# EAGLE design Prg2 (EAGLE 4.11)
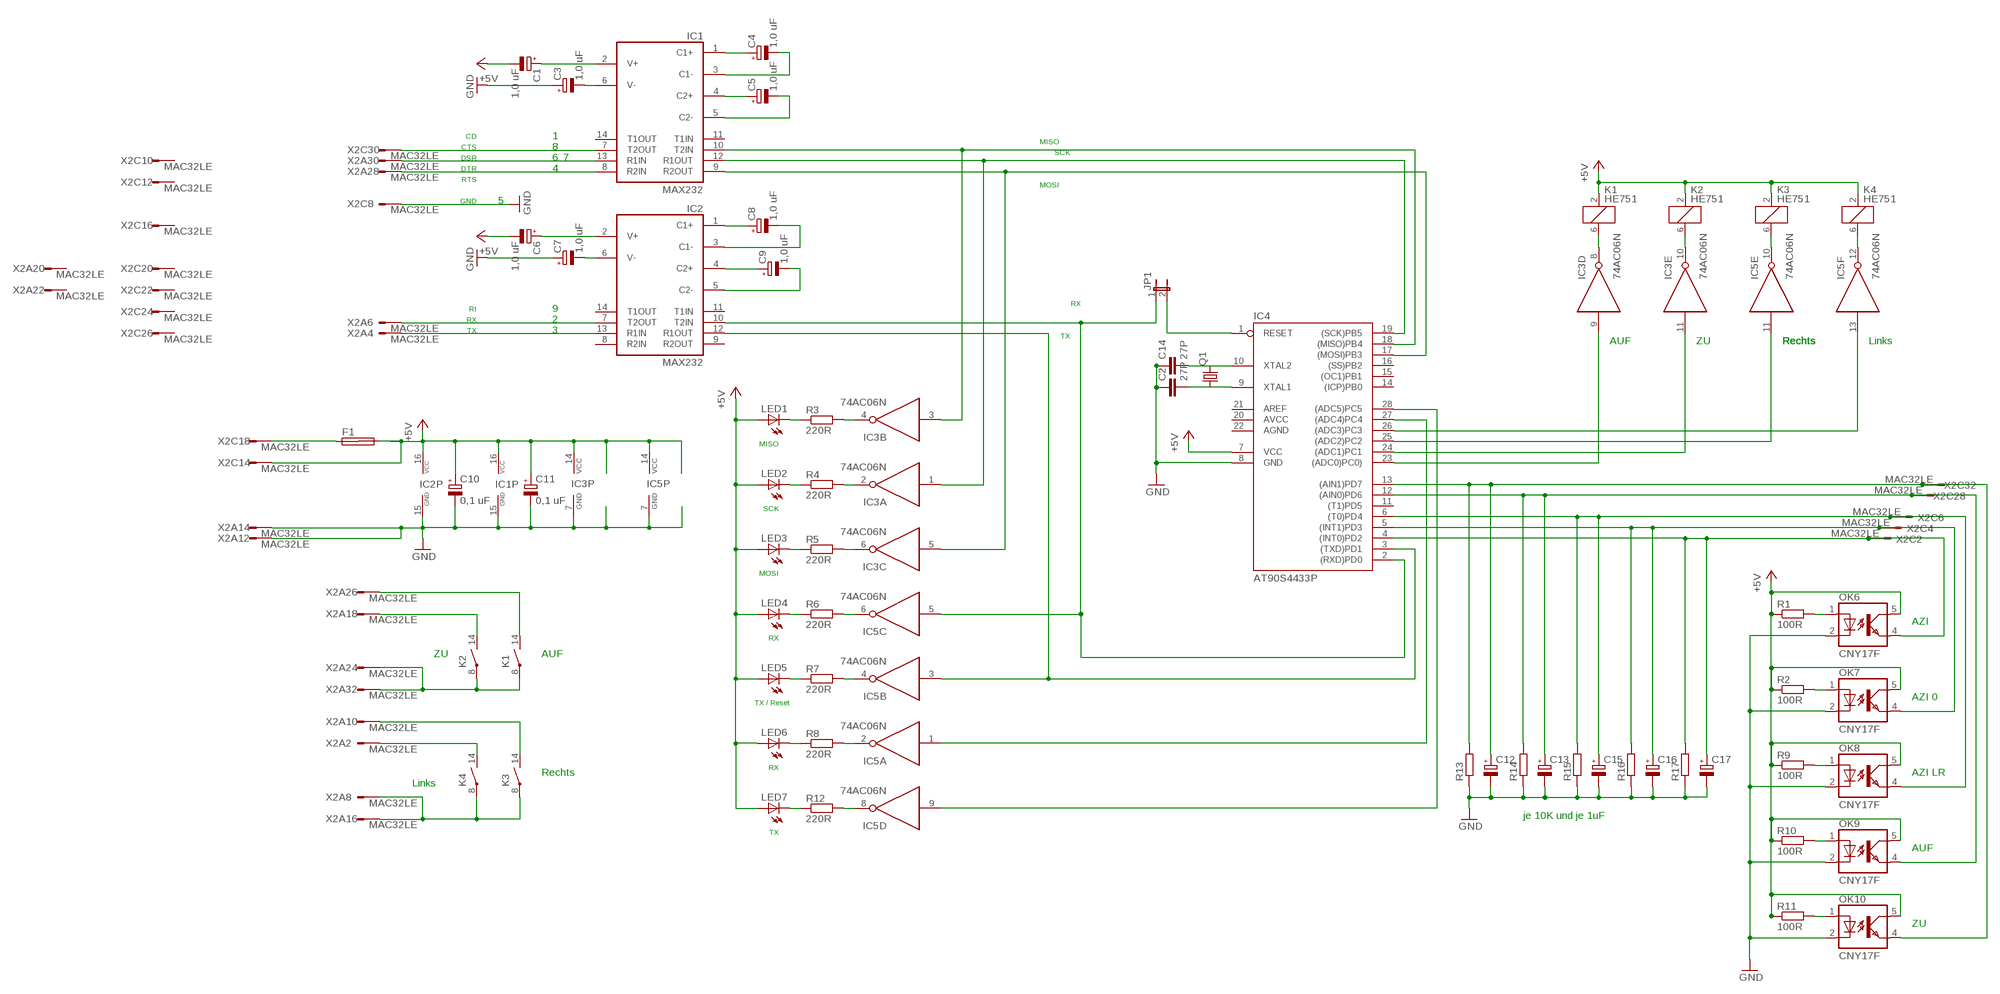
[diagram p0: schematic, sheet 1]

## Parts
C1  1,0 uF  CPOL-EUE2,5-6E  [E2,5-6E]
C2  27P  C-EU025-024X044  [C025-024X044]
C3  1,0 uF  CPOL-EUE2,5-6E  [E2,5-6E]
C4  1,0 uF  CPOL-EUE2,5-6E  [E2,5-6E]
C5  1,0 uF  CPOL-EUE2,5-6E  [E2,5-6E]
C6  1,0 uF  CPOL-EUE2,5-6E  [E2,5-6E]
C7  1,0 uF  CPOL-EUE2,5-6E  [E2,5-6E]
C8  1,0 uF  CPOL-EUE2,5-6E  [E2,5-6E]
C9  1,0 uF  CPOL-EUE2,5-6E  [E2,5-6E]
C10  0,1 uF  CPOL-EUE2,5-6E  [E2,5-6E]
C11  0,1 uF  CPOL-EUE2,5-6E  [E2,5-6E]
C12  CPOL-EUE2,5-6E  [E2,5-6E]
C13  CPOL-EUE2,5-6E  [E2,5-6E]
C14  27P  C-EU025-024X044  [C025-024X044]
C15  CPOL-EUE2,5-6E  [E2,5-6E]
C16  CPOL-EUE2,5-6E  [E2,5-6E]
C17  CPOL-EUE2,5-6E  [E2,5-6E]
F1  SHK20L  [SHK20L]
IC1  MAX232  [DIL16]
IC2  MAX232  [DIL16]
IC3  74AC06N  [DIL14]
IC4  AT90S4433P  [DIL28-3]
IC5  74AC06N  [DIL14]
JP1  JP1E  [JP1]
K1  HE751  [HE751]
K2  HE751  [HE751]
K3  HE751  [HE751]
K4  HE751  [HE751]
LED1  LED3MM  [LED3MM]
LED2  LED3MM  [LED3MM]
LED3  LED3MM  [LED3MM]
LED4  LED3MM  [LED3MM]
LED5  LED3MM  [LED3MM]
LED6  LED3MM  [LED3MM]
LED7  LED3MM  [LED3MM]
OK6  CNY17F  [DIL06]
OK7  CNY17F  [DIL06]
OK8  CNY17F  [DIL06]
OK9  CNY17F  [DIL06]
OK10  CNY17F  [DIL06]
Q1  CRYTALHC49S  [HC49/S]
R1  100R  R-EU_0204/7  [0204/7]
R2  100R  R-EU_0204/7  [0204/7]
R3  220R  R-EU_0207/2V  [0207/2V]
R4  220R  R-EU_0207/2V  [0207/2V]
R5  220R  R-EU_0207/2V  [0207/2V]
R6  220R  R-EU_0207/2V  [0207/2V]
R7  220R  R-EU_0207/2V  [0207/2V]
R8  220R  R-EU_0207/2V  [0207/2V]
R9  100R  R-EU_0204/7  [0204/7]
R10  100R  R-EU_0204/7  [0204/7]
R11  100R  R-EU_0204/7  [0204/7]
R12  220R  R-EU_0207/2V  [0207/2V]
R13  R-EU_0204/2V  [0204V]
R14  R-EU_0204/2V  [0204V]
R15  R-EU_0204/2V  [0204V]
R16  R-EU_0204/2V  [0204V]
R17  R-EU_0204/2V  [0204V]
X2  MAC32LE  [MAC32L]

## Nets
+5V: C1.- C6.- C10.+ C11.+ F1.2A IC1.16(VCC) IC2.16(VCC) IC3.14(P:VCC) IC4.7(VCC) IC5.14(P:VCC) K1.2 K2.2 K3.2 K4.2 LED1.A LED2.A LED3.A LED4.A LED5.A LED6.A LED7.A OK6.5(COL) OK7.5(COL) OK8.5(COL) OK9.5(COL) OK10.5(COL) R1.1 R2.1 R9.1 R10.1 R11.1 X2.C14
GND: C2.1 C3.+ C7.+ C10.- C11.- C12.- C13.- C14.1 C15.- C16.- C17.- IC1.15(GND) IC2.15(GND) IC3.7(P:GND) IC4.8(GND) IC5.7(P:GND) OK6.2(C) OK7.2(C) OK8.2(C) OK9.2(C) OK10.2(C) R13.1 R14.1 R15.1 R16.1 R17.1 X2.A12 X2.A14 X2.C8
N$1: C4.+ IC1.1(C1+)
N$2: C4.- IC1.3(C1-)
N$3: C5.+ IC1.4(C2+)
N$4: C5.- IC1.5(C2-)
N$5: C3.- IC1.6(V-)
N$6: C1.+ IC1.2(V+)
N$7: C6.+ IC2.2(V+)
N$8: C7.- IC2.6(V-)
N$9: C8.+ IC2.1(C1+)
N$10: C9.+ IC2.4(C2+)
N$11: C9.- IC2.5(C2-)
N$12: C8.- IC2.3(C1-)
N$13: K2.14(2:S) X2.A18
N$14: K3.8(2:P) K4.8(2:P) X2.A8 X2.A16
N$15: K3.14(2:S) X2.A10
N$16: K4.14(2:S) X2.A2
N$17: IC1.13(R1IN) X2.A30
N$18: IC1.8(R2IN) X2.A28
N$19: IC2.7(T2OUT) X2.A6
N$20: IC1.9(R2OUT) IC3.5(C:I) IC4.17((MOSI)PB3)
N$21: IC3.8(D:O) K1.6
N$22: IC3.10(E:O) K2.6
N$23: IC2.12(R1OUT) IC4.3((TXD)PD1) IC5.3(B:I)
N$24: IC2.10(T2IN) IC4.2((RXD)PD0) IC5.5(C:I) JP1.1
N$25: LED1.K(C) R3.1
N$26: IC3.4(B:O) R3.2
N$27: LED2.K(C) R4.1
N$28: IC3.2(A:O) R4.2
N$29: LED3.K(C) R5.1
N$30: IC3.6(C:O) R5.2
N$31: LED4.K(C) R6.1
N$32: IC5.6(C:O) R6.2
N$33: LED5.K(C) R7.1
N$34: IC5.4(B:O) R7.2
N$35: C14.2 IC4.10(XTAL2) Q1.2
N$36: C2.2 IC4.9(XTAL1) Q1.1
N$37: IC3.9(D:I) IC4.23((ADC0)PC0))
N$38: IC5.12(F:O) K4.6
N$39: IC4.26((ADC3)PC3) IC5.13(F:I)
N$40: IC5.10(E:O) K3.6
N$41: IC1.10(T2IN) IC3.3(B:I) IC4.18((MISO)PB4)
N$42: IC4.1(RESET) JP1.2
N$43: IC5.2(A:O) R8.2
N$44: IC5.8(D:O) R12.2
N$45: LED6.K(C) R8.1
N$46: LED7.K(C) R12.1
N$47: IC4.27((ADC4)PC4) IC5.1(A:I)
N$48: IC4.28((ADC5)PC5) IC5.9(D:I)
N$49: IC1.12(R1OUT) IC3.1(A:I) IC4.19((SCK)PB5)
N$50: IC3.11(E:I) IC4.24((ADC1)PC1)
N$51: IC4.25((ADC2)PC2) IC5.11(E:I)
N$52: OK6.1(A) R1.2
N$53: OK7.1(A) R2.2
N$54: OK8.1(A) R9.2
N$55: OK9.1(A) R10.2
N$56: OK10.1(A) R11.2
N$57: F1.1A X2.C18
N$59: C16.+ IC4.5((INT1)PD3) OK7.4(EMIT) R16.2 X2.C4
N$60: C15.+ IC4.6((T0)PD4) OK8.4(EMIT) R15.2 X2.C6
N$61: C13.+ IC4.12((AIN0)PD6) OK9.4(EMIT) R14.2 X2.C28
N$62: K1.14(2:S) X2.A26
N$63: C12.+ IC4.13((AIN1)PD7) OK10.4(EMIT) R13.2 X2.C32
N$64: K1.8(2:P) K2.8(2:P) X2.A24 X2.A32
N$65: IC1.7(T2OUT) X2.C30
N$66: IC2.13(R1IN) X2.A4
N$67: C17.+ IC4.4((INT0)PD2) OK6.4(EMIT) R17.2 X2.C2
Unconnected: F1.1B F1.2B IC1.11(T1IN) IC1.14(T1OUT) IC2.8(R2IN) IC2.9(R2OUT) IC2.11(T1IN) IC2.14(T1OUT) IC3.12(F:O) IC3.13(F:I) IC4.11((T1)PD5) IC4.14((ICP)PB0) IC4.15((OC1)PB1) IC4.16((SS)PB2) X2.A20 X2.A22 X2.C10 X2.C12 X2.C16 X2.C20 X2.C22 X2.C24 X2.C26

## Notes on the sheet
- CD | 1 | MISO
- CTS | 8 | SCK
- DSR | 6 | 7
- DTR | 4
- RTS | MOSI
- GND | 5
- RX
- RI | 9
- RX | 2
- TX | 3 | TX
- AUF | ZU | Rechts | Rechts | Links
- MISO
- SCK
- MOSI
- AZI
- RX
- ZU | AUF
- TX / Reset | AZI 0
- RX
- Rechts | AZI LR
- Links
- je 10K und je 1uF
- TX
- AUF
- ZU

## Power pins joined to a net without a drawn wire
AGND: IC4.22(AGND)
AREF: IC4.21(AREF)
AVCC: IC4.20(AVCC)

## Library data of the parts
C1 C3-C13 C15-C17 = rcl:CPOL-EU: POLARIZED CAPACITOR, European symbol
C2 C14 = rcl:C-EU: CAPACITOR, European symbol
F1 = fuse:SHK20L: FUSE HOLDER 5 x 20 mm, SH contact, SHH1 Schukat, E1073 Buerklin
IC1 IC2 = maxim:MAX232: RS232 TRANSEIVER
IC3 IC5 = 74xx-eu:74*06: Hex INVERTER, open collector high-voltage output
IC4 = atmel:AT90S4433: MICROCONTROLLER 4 Kbytes FLASH 128 bytes SRAM 256 bytes EEPROM UART 6-channel 10 bit ADC
JP1 = jumper:JP1E: JUMPER
K1-K4 = relay:HE751: RELAY reed, 1 x norm. open, Hamlin
LED1-LED7 = led:LED: LED
OK6-OK10 = optocoupler:CNY17F: SIEMENS OPTO COUPLER
Q1 = crystal:CRYTAL: CRYSTAL
R1-R17 = rcl:R-EU_: RESISTOR, European symbol
X2 = con-vg:MAC32LE: CONNECTOR male, 32 pins, single, type D, rows AC, grid 5.08 mm with mounting clip

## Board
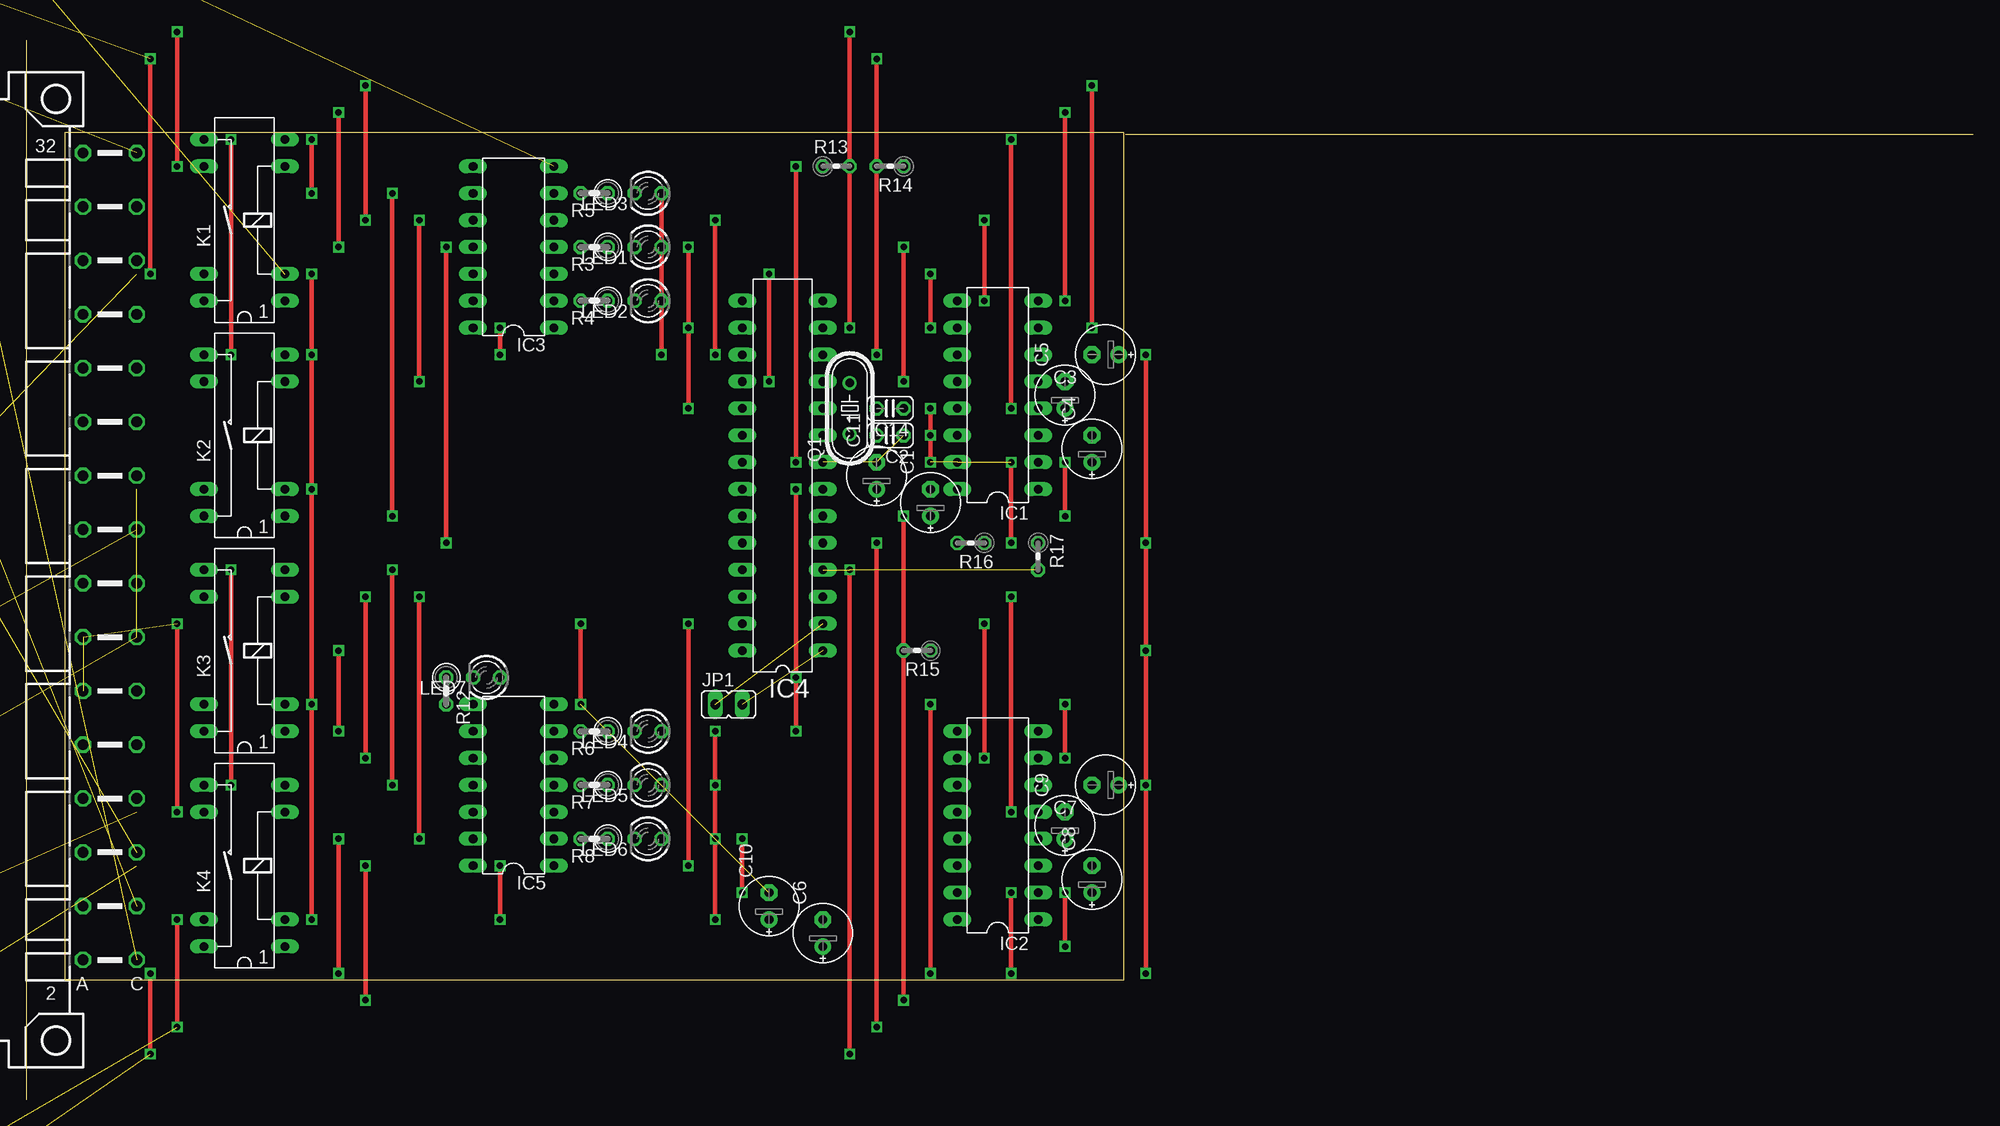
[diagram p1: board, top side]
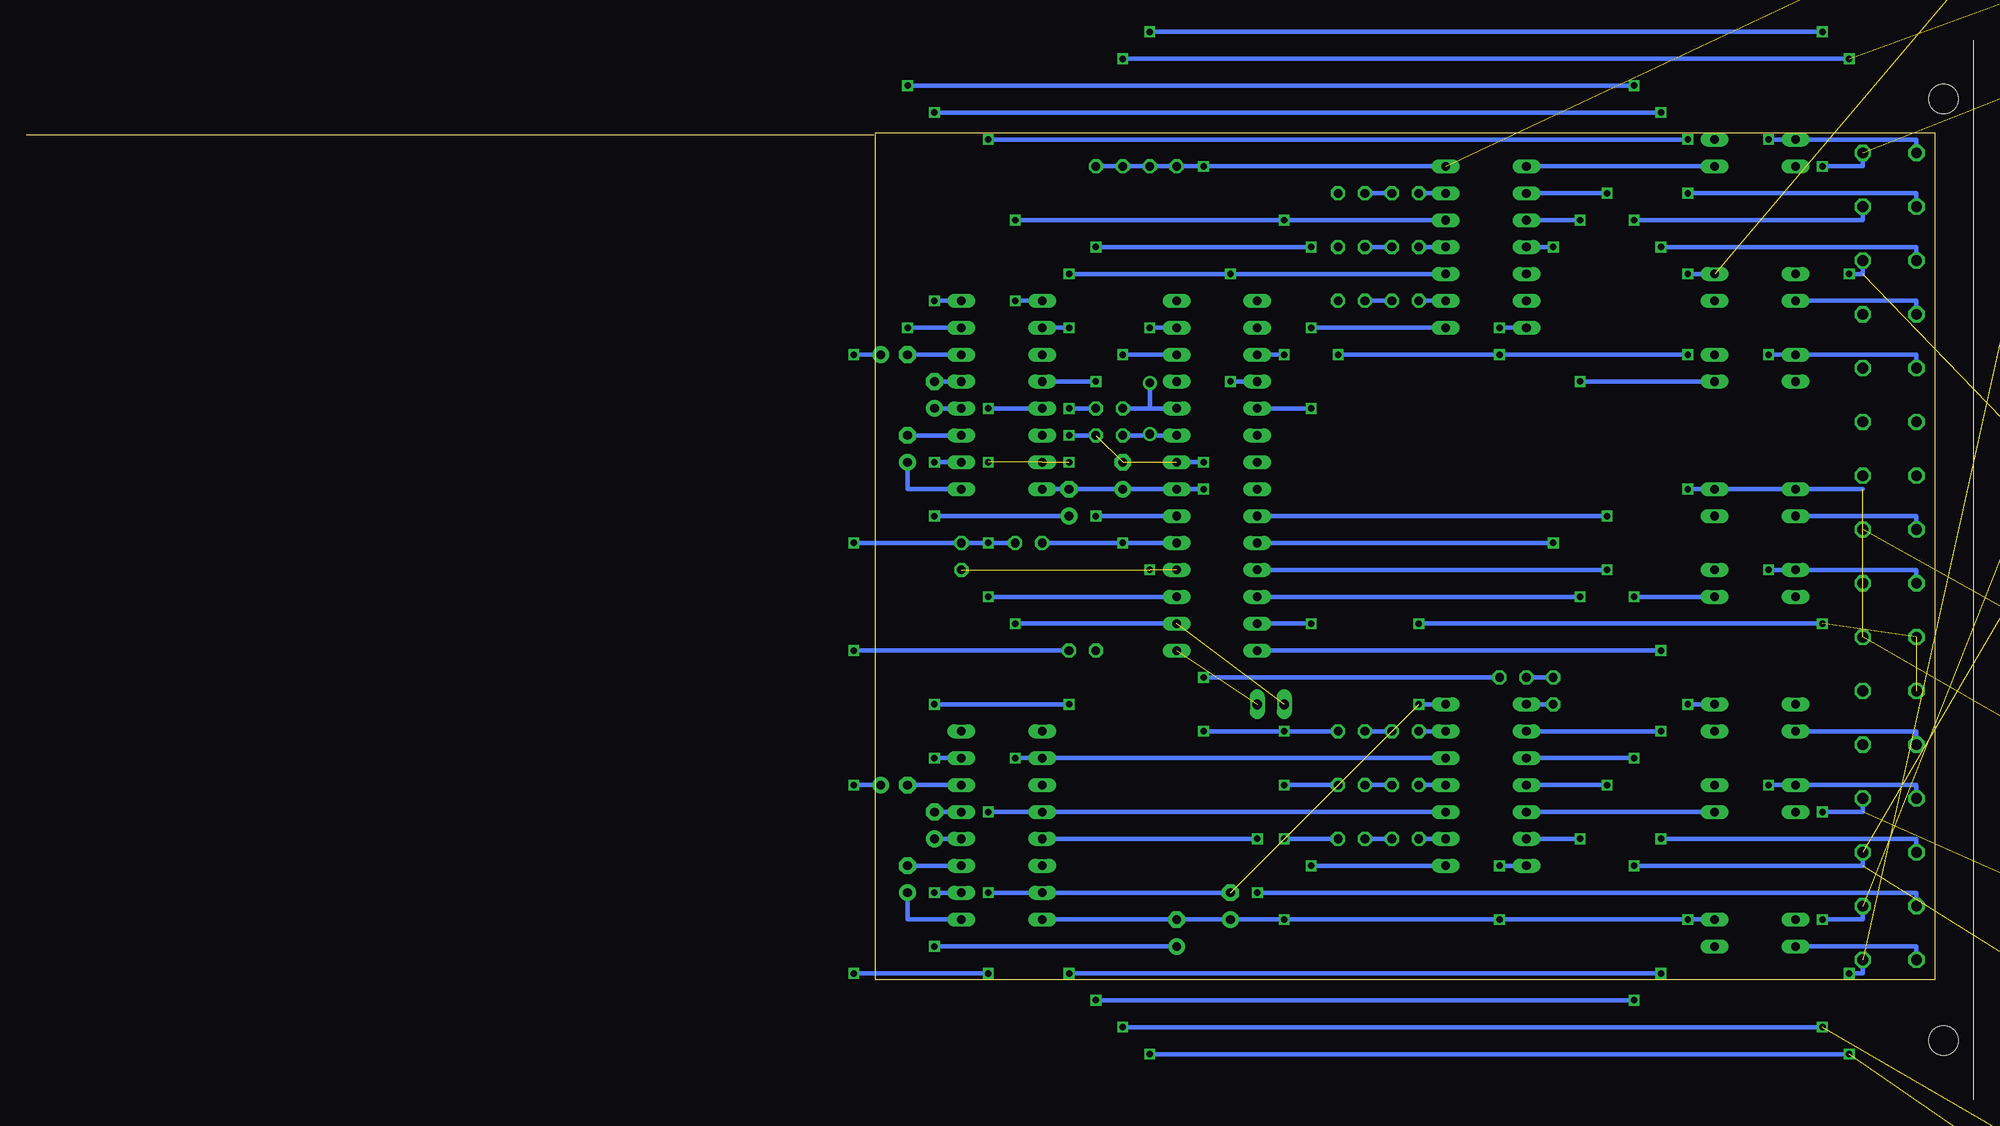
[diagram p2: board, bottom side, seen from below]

Size 183.76 x 100.03 mm. Coordinates in mm from the lower left corner, seen from the top.
Outline: 183.76,91.12 103.76,91.12
Outline: 3.59,11.28 103.59,11.28 103.59,91.28 3.59,91.28 3.59,11.28
Copper layers (1*16): Top 0.035mm / dielectric 1.5mm / Bottom 0.035mm
Design rules "default": minimum track width 10mil, minimum drill 24mil, track to track 8mil, track to pad 8mil, pad to pad 8mil, via to via 8mil, smd to smd 8mil, copper to edge 40mil, drill to drill 8mil, minimum pad ring 10mil, minimum via ring 8mil, stop-mask expansion 4mil, vias tented up to drill 0mil, thermal gap 10mil

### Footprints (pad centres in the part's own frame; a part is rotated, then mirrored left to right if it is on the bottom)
E2,5-6E = drill 0.813 pad 1.575 round: + -1.27,0 | drill 0.813 pad 1.575 octagon: - 1.27,0
C025-024X044 = drill 0.813 octagon: 1 -1.27,0; 2 1.27,0
SHK20L = drill 1.321 pad 2.54 long: 1A -10.414,0; 1B -5.334,0; 2A 10.414,0; 2B 5.334,0
DIL16 = drill 0.813 long: 1 -8.89,-3.81; 2 -6.35,-3.81; 3 -3.81,-3.81; 4 -1.27,-3.81; 5 1.27,-3.81; 6 3.81,-3.81; 7 6.35,-3.81; 8 8.89,-3.81; 9 8.89,3.81; 10 6.35,3.81; 11 3.81,3.81; 12 1.27,3.81; 13 -1.27,3.81; 14 -3.81,3.81; 15 -6.35,3.81; 16 -8.89,3.81
DIL14 = drill 0.813 long: 1 -7.62,-3.81; 2 -5.08,-3.81; 3 -2.54,-3.81; 4 0,-3.81; 5 2.54,-3.81; 6 5.08,-3.81; 7 7.62,-3.81; 8 7.62,3.81; 9 5.08,3.81; 10 2.54,3.81; 11 0,3.81; 12 -2.54,3.81; 13 -5.08,3.81; 14 -7.62,3.81
DIL28-3 = drill 0.813 long: 1 -16.51,-3.81; 2 -13.97,-3.81; 3 -11.43,-3.81; 4 -8.89,-3.81; 5 -6.35,-3.81; 6 -3.81,-3.81; 7 -1.27,-3.81; 8 1.27,-3.81; 9 3.81,-3.81; 10 6.35,-3.81; 11 8.89,-3.81; 12 11.43,-3.81; 13 13.97,-3.81; 14 16.51,-3.81; 15 16.51,3.81; 16 13.97,3.81; 17 11.43,3.81; 18 8.89,3.81; 19 6.35,3.81; 20 3.81,3.81; 21 1.27,3.81; 22 -1.27,3.81; 23 -3.81,3.81; 24 -6.35,3.81; 25 -8.89,3.81; 26 -11.43,3.81; 27 -13.97,3.81; 28 -16.51,3.81
JP1 = drill 0.914 long: 1 0,-1.27; 2 0,1.27
HE751 = drill 0.813 long: 1 -7.62,-3.81; 2 -5.08,-3.81; 6 5.08,-3.81; 7 7.62,-3.81; 8 7.62,3.81; 9 5.08,3.81; 13 -5.08,3.81; 14 -7.62,3.81
LED3MM = drill 0.813 octagon: A -1.27,0; K 1.27,0
DIL06 = drill 0.813 long: 1 -2.54,-3.81; 2 0,-3.81; 3 2.54,-3.81; 4 2.54,3.81; 5 0,3.81; 6 -2.54,3.81
HC49/S = drill 0.813 round: 1 -2.413,0; 2 2.413,0
0204/7 = drill 0.813 octagon: 1 -3.81,0; 2 3.81,0
0207/2V = drill 0.813 octagon: 1 -1.27,0; 2 1.27,0
0204V = drill 0.813 octagon: 1 -1.27,0; 2 1.27,0
MAC32L = drill 1.016 octagon: A2 -2.54,36.83; A4 -2.54,31.75; A6 -2.54,26.67; A8 -2.54,21.59; A10 -2.54,16.51; A12 -2.54,11.43; A14 -2.54,6.35; A16 -2.54,1.27; A18 -2.54,-3.81; A20 -2.54,-8.89; A22 -2.54,-13.97; A24 -2.54,-19.05; A26 -2.54,-24.13; A28 -2.54,-29.21; A30 -2.54,-34.29; A32 -2.54,-39.37; C2 -7.62,36.83; C4 -7.62,31.75; C6 -7.62,26.67; C8 -7.62,21.59; C10 -7.62,16.51; C12 -7.62,11.43; C14 -7.62,6.35; C16 -7.62,1.27; C18 -7.62,-3.81; C20 -7.62,-8.89; C22 -7.62,-13.97; C24 -7.62,-19.05; C26 -7.62,-24.13; C28 -7.62,-29.21; C30 -7.62,-34.29; C32 -7.62,-39.37 | hole 2.794: 0,44.45; 0,-44.45

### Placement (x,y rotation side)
C1  85.34,56.36 90 top
C2  81.53,62.71 180 top
C3  101.85,70.33 180 top
C4  100.58,61.44 90 top
C5  98.04,66.52 90 top
C6  75.18,15.72 90 top
C7  101.85,29.69 180 top
C8  100.58,20.8 90 top
C9  98.04,25.88 90 top
C10  70.1,18.26 90 top
C11  80.26,58.9 90 top
C12  not placed on the board
C13  not placed on the board
C14  81.53,65.25 180 top
C15  not placed on the board
C16  not placed on the board
C17  not placed on the board
F1  not placed on the board
IC1  91.69,66.52 90 top
IC2  91.69,25.88 90 top
IC3  45.97,80.49 90 top
IC4  71.37,58.9 90 top
IC5  45.97,29.69 90 top
JP1  66.29,37.31 270 top
K1  20.57,83.03 90 top
K2  20.57,62.71 90 top
K3  20.57,42.39 90 top
K4  20.57,22.07 90 top
LED1  58.67,80.49 180 top
LED2  58.67,75.41 180 top
LED3  58.67,85.57 180 top
LED4  58.67,34.77 180 top
LED5  58.67,29.69 180 top
LED6  58.67,24.61 180 top
LED7  43.43,39.85 180 top
OK6  not placed on the board
OK7  not placed on the board
OK8  not placed on the board
OK9  not placed on the board
OK10  not placed on the board
Q1  77.72,65.25 90 top
R1  not placed on the board
R2  not placed on the board
R3  53.59,80.49 180 top
R4  53.59,75.41 180 top
R5  53.59,85.57 180 top
R6  53.59,34.77 180 top
R7  53.59,29.69 180 top
R8  53.59,24.61 180 top
R9  not placed on the board
R10  not placed on the board
R11  not placed on the board
R12  39.62,38.58 270 top
R13  76.45,88.11 0 top
R14  81.53,88.11 180 top
R15  84.07,42.39 180 top
R16  89.15,52.55 180 top
R17  95.5,51.28 270 top
X2  2.79,50.01 180 top

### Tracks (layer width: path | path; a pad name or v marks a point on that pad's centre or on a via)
+5V  (via drill 0.61)  (12 unrouted)
  Top 0.406: v26.92,77.95 v26.92,70.33 v26.92,57.63 v26.92,37.31 v26.92,16.99 | v44.7,16.99 v44.7,22.07 | v65.02,16.99 v65.02,24.61 v65.02,29.69 v65.02,34.77 | v72.64,57.63 v72.64,39.85 v72.64,34.77 | v44.7,70.33 v44.7,72.87 | v59.94,70.33 LED2.A LED1.A LED3.A
  Bottom 0.406: K2.2 v26.92,57.63 K2.2 | K4.2 v26.92,16.99 v44.7,16.99 v65.02,16.99 C10.+ | LED4.A v65.02,34.77 v72.64,34.77 | v72.64,57.63 IC4.7 C11.+ C1.- IC1.16 | v72.64,39.85 LED7.A | v59.94,70.33 v44.7,70.33 v26.92,70.33 | K2.2 10.41,57.63 | v44.7,72.87 IC3.14 | C10.+ C6.- | C6.- IC2.16 | C10.+ C6.- | v44.7,22.07 IC5.14 | v26.92,77.95 K1.2 v26.92,77.95 | v26.92,37.31 K3.2 v26.92,37.31 | v65.02,24.61 LED6.A v65.02,24.61 | v65.02,29.69 LED5.A v65.02,29.69
GND  (via drill 0.61)  (17 unrouted)
  Top 0.406: v92.96,52.55 v92.96,60.17 | v105.66,70.33 v105.66,52.55 v105.66,42.39 v105.66,29.69 v105.66,11.91 | v92.96,19.53 v92.96,11.91 | v72.64,60.17 v72.64,88.11 | v85.34,60.17 v85.34,62.71 v85.34,65.25 | v14.22,27.15 v14.22,44.93 | v52.32,44.93 v52.32,37.31
  Bottom 0.406: v105.66,70.33 C3.+ | v105.66,29.69 C7.+ | R17.1 v92.96,52.55 R16.1 R17.1 | v105.66,52.55 R17.1 | v92.96,11.91 v105.66,11.91 | v72.64,60.17 IC4.8 | v85.34,65.25 C14.1 | C2.1 v85.34,62.71 | R14.1 R13.1 v72.64,88.11 IC3.7 | v105.66,42.39 R15.1 | C10.- IC2.15 v92.96,19.53 | X2.C8 10.41,27.15 v14.22,27.15 | v14.22,44.93 v52.32,44.93 | v52.32,37.31 IC5.7
N$1
  Bottom 0.406: C4.+ 100.58,57.63 IC1.1
N$2
  Bottom 0.406: IC1.3 C4.-
N$3
  Bottom 0.406: IC1.4 C5.+
N$4
  Bottom 0.406: IC1.5 C5.-
N$5
  Bottom 0.406: IC1.6 C3.-
N$6  (via drill 0.61)
  Top 0.406: v98.04,55.09 v98.04,60.17
  Bottom 0.406: C1.+ v98.04,55.09 | v98.04,60.17 IC1.2
N$7  (via drill 0.61)
  Top 0.406: v98.04,14.45 v98.04,19.53
  Bottom 0.406: C6.+ v98.04,14.45 | v98.04,19.53 IC2.2
N$8
  Bottom 0.406: IC2.6 C7.-
N$9
  Bottom 0.406: IC2.1 100.58,16.99 C8.+
N$10
  Bottom 0.406: IC2.4 C9.+
N$11
  Bottom 0.406: IC2.5 C9.-
N$12
  Bottom 0.406: IC2.3 C8.-
N$13
  Bottom 0.406: K2.14 5.33,55.09 X2.A18
N$14  (via drill 0.61)
  Top 0.406: v19.3,29.69 v19.3,50.01
  Bottom 0.406: K3.8 v19.3,50.01 5.33,50.01 X2.A16 | X2.A8 5.33,29.69 v19.3,29.69 K4.8
N$15
  Bottom 0.406: K3.14 5.33,34.77 X2.A10
N$16
  Bottom 0.406: K4.14 5.33,14.45 X2.A2
N$17  (via drill 0.61)
  Top 0.406: v92.96,90.65 v92.96,65.25 | v26.92,85.57 v26.92,90.65
  Bottom 0.406: v92.96,65.25 IC1.13 | v26.92,90.65 v92.96,90.65 | v26.92,85.57 5.33,85.57 X2.A30
N$18  (via drill 0.61)
  Top 0.406: v98.04,93.19 v98.04,75.41 | v29.46,80.49 v29.46,93.19
  Bottom 0.406: v98.04,75.41 IC1.8 | v29.46,93.19 v98.04,93.19 | v29.46,80.49 5.33,80.49 X2.A28
N$19  (via drill 0.61)
  Top 0.406: v98.04,37.31 v98.04,32.23 | v85.34,11.91 v85.34,37.31 | v29.46,24.61 v29.46,11.91
  Bottom 0.406: v98.04,32.23 IC2.7 | v85.34,37.31 v98.04,37.31 | v29.46,11.91 v85.34,11.91 | v29.46,24.61 5.33,24.61 X2.A6
N$20  (via drill 0.61)
  Top 0.406: v90.42,83.03 v90.42,75.41 | v65.02,83.03 v65.02,70.33
  Bottom 0.406: v90.42,75.41 IC1.9 | IC3.5 v65.02,83.03 v90.42,83.03 | v65.02,70.33 IC4.17
N$21
  Bottom 0.406: K1.6 IC3.8
N$22  (via drill 0.61)
  Top 0.406: v37.08,67.79 v37.08,83.03
  Bottom 0.406: v37.08,83.03 IC3.10 | K2.6 v37.08,67.79
N$23  (via drill 0.61)
  Top 0.406: v92.96,27.15 v92.96,47.47
  Bottom 0.406: IC5.3 v92.96,27.15 IC2.12 | v92.96,47.47 IC4.3
N$24  (via drill 0.61)  (1 unrouted)
  Top 0.406: v90.42,32.23 v90.42,44.93
  Bottom 0.406: IC5.5 v90.42,32.23 IC2.10 | v90.42,44.93 IC4.2
N$25
  Bottom 0.406: R3.1 LED1.K
N$26
  Bottom 0.406: IC3.4 R3.2
N$27
  Bottom 0.406: R4.1 LED2.K
N$28
  Bottom 0.406: IC3.2 R4.2
N$29
  Bottom 0.406: R5.1 LED3.K
N$30
  Bottom 0.406: IC3.6 R5.2
N$31
  Bottom 0.406: R6.1 LED4.K
N$32
  Bottom 0.406: IC5.6 R6.2
N$33
  Bottom 0.406: R7.1 LED5.K
N$34
  Bottom 0.406: IC5.4 R7.2
N$35
  Bottom 0.406: IC4.10 77.72,65.25 | 77.72,65.25 C14.2 | 77.72,67.79 Q1.2 77.72,65.25
N$36
  Bottom 0.406: 77.72,62.71 C2.2 | 77.72,62.71 Q1.1 | IC4.9 77.72,62.71
N$37  (via drill 0.61)
  Top 0.406: v34.54,55.09 v34.54,85.57
  Bottom 0.406: IC4.23 v34.54,55.09 | v34.54,85.57 IC3.9
N$38
  Bottom 0.406: K4.6 IC5.12
N$39  (via drill 0.61)
  Top 0.406: v37.08,24.61 v37.08,47.47
  Bottom 0.406: v37.08,24.61 IC5.13 | v37.08,47.47 IC4.26
N$40  (via drill 0.61)
  Top 0.406: v32,32.23 v32,47.47
  Bottom 0.406: v32,32.23 IC5.10 | v32,47.47 K3.6
N$41  (via drill 0.61)
  Top 0.406: v70.1,77.95 v70.1,67.79 | v85.34,77.95 v85.34,72.87
  Bottom 0.406: IC3.3 v70.1,77.95 v85.34,77.95 | v70.1,67.79 IC4.18 | v85.34,72.87 IC1.10
N$42  (1 unrouted)
N$43
  Bottom 0.406: IC5.2 R8.2
N$44
  Bottom 0.406: R12.2 IC5.8
N$45
  Bottom 0.406: R8.1 LED6.K
N$46
  Bottom 0.406: R12.1 LED7.K
N$47  (via drill 0.61)
  Top 0.406: v62.48,22.07 v62.48,44.93
  Bottom 0.406: IC5.1 v62.48,22.07 | v62.48,44.93 IC4.27
N$48  (via drill 0.61)
  Top 0.406: v29.46,34.77 v29.46,42.39
  Bottom 0.406: v29.46,34.77 IC5.9 | v29.46,42.39 IC4.28
N$49  (via drill 0.61)
  Top 0.406: v82.8,80.49 v82.8,67.79 | v62.48,65.25 v62.48,72.87 v62.48,80.49
  Bottom 0.406: v82.8,67.79 IC1.12 | v62.48,80.49 v82.8,80.49 | v62.48,65.25 IC4.19 | IC3.1 v62.48,72.87
N$50  (via drill 0.61)
  Top 0.406: v39.62,52.55 v39.62,80.49
  Bottom 0.406: IC4.24 v39.62,52.55 | v39.62,80.49 IC3.11
N$51  (via drill 0.61)
  Top 0.406: v34.54,50.01 v34.54,29.69
  Bottom 0.406: IC4.25 v34.54,50.01 | v34.54,29.69 IC5.11
N$52  (1 unrouted)
N$53  (1 unrouted)
N$54  (1 unrouted)
N$55  (1 unrouted)
N$56  (1 unrouted)
N$57  (1 unrouted)
N$59  (via drill 0.61)  (2 unrouted)
  Top 0.406: v80.26,6.83 v80.26,52.55 | v14.22,6.83 v14.22,16.99
  Bottom 0.406: IC4.5 v80.26,52.55 R16.2 | v14.22,6.83 v80.26,6.83 | v14.22,16.99 10.41,16.99 X2.C4
N$60  (via drill 0.61)  (2 unrouted)
  Top 0.406: v82.8,9.37 R15.2 | R15.2 v82.8,55.09 R15.2 | v32,22.07 v32,9.37
  Bottom 0.406: v82.8,55.09 IC4.6 | v32,9.37 v82.8,9.37 | v32,22.07 10.41,22.07 X2.C6
N$61  (via drill 0.61)  (2 unrouted)
  Top 0.406: R14.2 v80.26,98.27 R14.2 | R14.2 v80.26,70.33 | v11.68,77.95 v11.68,98.27
  Bottom 0.406: v80.26,70.33 IC4.12 | v11.68,98.27 v80.26,98.27 | v11.68,77.95 10.41,77.95 X2.C28
N$62
  Bottom 0.406: K1.14 5.33,75.41 X2.A26
N$63  (via drill 0.61)  (2 unrouted)
  Top 0.406: R13.2 v77.72,100.81 R13.2 | R13.2 v77.72,72.87 | v14.22,88.11 v14.22,100.81
  Bottom 0.406: v77.72,72.87 IC4.13 | v14.22,100.81 v77.72,100.81 | v14.22,88.11 10.41,88.11 X2.C32
N$64  (via drill 0.61)
  Top 0.406: v19.3,70.33 v19.3,90.65
  Bottom 0.406: X2.A32 5.33,90.65 v19.3,90.65 K1.8 | X2.A24 5.33,70.33 v19.3,70.33 K2.8
N$65  (via drill 0.61)
  Top 0.406: v32,83.03 v32,95.73 | v100.58,95.73 v100.58,72.87
  Bottom 0.406: X2.C30 10.41,83.03 v32,83.03 | v32,95.73 v100.58,95.73 | v100.58,72.87 IC1.7
N$66  (via drill 0.61)
  Top 0.406: v67.56,19.53 v67.56,24.61
  Bottom 0.406: X2.A4 5.33,19.53 v67.56,19.53 | v67.56,24.61 IC2.13
N$67  (via drill 0.61)  (4 unrouted)
  Top 0.406: v77.72,4.29 v77.72,50.01 | v11.68,4.29 v11.68,11.91
  Bottom 0.406: v11.68,4.29 v77.72,4.29 | v11.68,11.91 10.41,11.91 X2.C2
